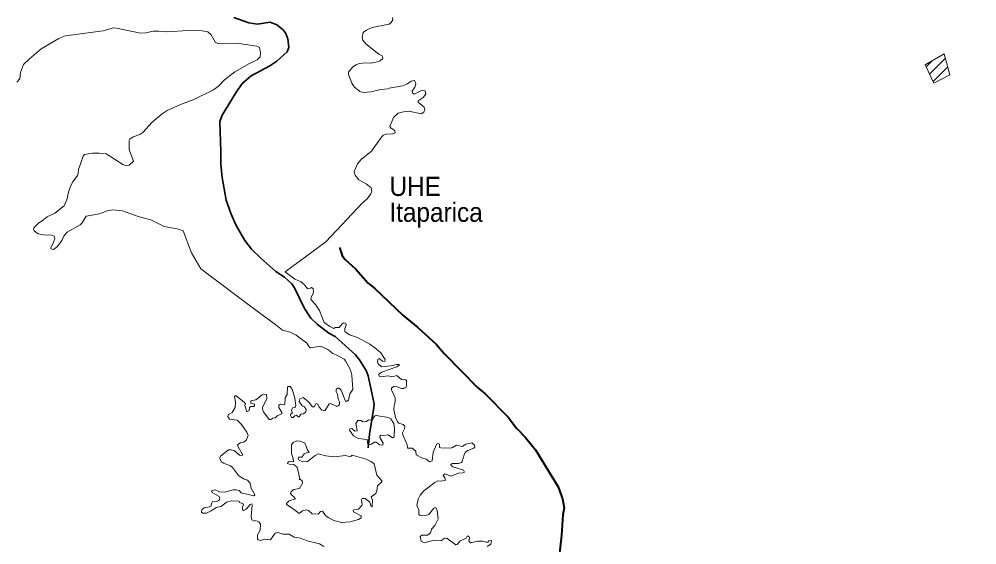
# Model space of a CAD drawing. Extents: x -1643653 to 4543381, y 1624270 to 13878484.
# Drawn here: x 577542 to 582541, y 8916252 to 8918997 of the extents above; entities that cross this region are included whole.
import ezdxf
from ezdxf.enums import TextEntityAlignment as Align

# ---------------------------------------------------------------- set-up
doc = ezdxf.new("R2010")
doc.units = 0
doc.header["$LTSCALE"] = 200
doc.linetypes.add('LONG_DASH_SHORT_DASH', pattern=[9.9, 6, -1.2, 1.5, -1.2])
doc.layers.add('6', color=7, linetype='Continuous', lineweight=13)
doc.layers.add('60', color=7, linetype='Continuous', lineweight=13)

msp = doc.modelspace()

# ---------------------------------------------------------------- linework, layer by layer
at = {"layer": '6'}
for p, q in [((582276.5, 8918748), (582308.9, 8918780.4)), ((582294.7, 8918709.6), (582376.4, 8918791.3)), ((582312.9, 8918671.2), (582388.6, 8918746.9)), ((578490.1, 8917693.2), (578784.8, 8917471.3))]:
    msp.add_line(p, q, dxfattribs=at)
at = {"layer": '6', "linetype": 'LONG_DASH_SHORT_DASH', "lineweight": 35}
msp.add_lwpolyline([(578662.2, 8919005.9), (578740.7, 8918978.3), (578785.6, 8918971), (578853, 8918981.3), (578886.8, 8918967.1), (578920.4, 8918940.8), (578934.7, 8918922.2), (578944.3, 8918894), (578949.9, 8918849), (578940.4, 8918826.6), (578886.4, 8918777.3), (578850.5, 8918753.1), (578753.6, 8918701.1), (578706.1, 8918660.5), (578672.4, 8918612.1), (578601.1, 8918496.3), (578590.2, 8918462.5), (578595.4, 8918305.1), (578594.6, 8918237.6), (578601, 8918170.3), (578622.6, 8918051), (578647.7, 8917978.3), (578674.1, 8917918.6), (578719.9, 8917840.4), (578754.5, 8917795.8), (578802.9, 8917748.3), (578882.1, 8917679.1), (578927.3, 8917649), (578965.1, 8917614.7), (578979.8, 8917594.3), (579031.7, 8917485.4), (579064.8, 8917435.4), (579097.3, 8917404.1), (579157.9, 8917356.5), (579191.2, 8917339.2), (579297.6, 8917243.3), (579319.2, 8917218.6), (579353.8, 8917162), (579364.1, 8917134.3), (579394.4, 8916988.5), (579393.5, 8916968.2), (579370.6, 8916829.9), (579363.6, 8916758.3)], dxfattribs=at)
at = {"layer": '6'}
for points in [[(579295.8, 8918182.3), (579291.5, 8918200.6), (579307.5, 8918242), (579327.8, 8918264.5), (579381, 8918307.3), (579422.1, 8918366.6), (579442.8, 8918390.3), (579458.5, 8918396.8), (579492.9, 8918398.1), (579504.6, 8918403.3), (579502.1, 8918414), (579491.2, 8918423.6), (579484.3, 8918425.4), (579477, 8918437), (579495.2, 8918484.1), (579521.1, 8918506.1), (579547.4, 8918513.1), (579576, 8918516.1), (579639.6, 8918503.2), (579655.1, 8918511.3), (579659.8, 8918523.3), (579656.9, 8918537.9), (579624.6, 8918563), (579625.6, 8918570.8), (579651.2, 8918588.3), (579665, 8918605.2), (579661.2, 8918622.9), (579642.5, 8918623.8), (579604.2, 8918605.7), (579595.9, 8918611.7), (579593.3, 8918620.7), (579607.5, 8918642.4), (579612.3, 8918657.9), (579611.4, 8918665.7), (579604.8, 8918676.1), (579589, 8918673.1), (579568.6, 8918658.8), (579543.1, 8918648), (579472.5, 8918637.1), (579466.2, 8918633.7), (579429.9, 8918630.3), (579378.4, 8918616.5), (579337.7, 8918613.6), (579320.5, 8918618.6), (579290.7, 8918643.6), (579278.5, 8918662.3), (579260.9, 8918708.6), (579260.8, 8918720.6), (579283.7, 8918747.4), (579301.1, 8918759.1), (579316.6, 8918764.7), (579347.4, 8918769.1), (579377.5, 8918767.2), (579405.6, 8918771.7), (579426.4, 8918779), (579440.6, 8918790.7), (579436.8, 8918806.1), (579419.9, 8918814.4), (579352.2, 8918867.1), (579336.1, 8918887.9), (579332.2, 8918899.6), (579337.8, 8918926.9), (579354.2, 8918939.8), (579384.9, 8918954.1), (579473.2, 8918970.6), (579483.9, 8918978.8), (579491.7, 8918993.8), (579490.8, 8919005.1)], [(577530.1, 8918668.4), (577544.6, 8918685.7), (577549.6, 8918717.7), (577565.3, 8918759.2), (577595.3, 8918789.2), (577657.2, 8918841.2), (577748.5, 8918896.2), (577783.4, 8918909.1), (577980.6, 8918936.4), (578032.5, 8918951.5), (578049.8, 8918950.2), (578175.2, 8918923), (578202.8, 8918925.1), (578240.9, 8918933.3), (578269.5, 8918934.2), (578316.9, 8918929.9), (578421.6, 8918937.2), (578497.7, 8918935.9), (578526.2, 8918930.3), (578544.1, 8918914.6), (578567.3, 8918875.5), (578580.7, 8918869.8), (578675.8, 8918871.9), (578783.4, 8918855.9), (578796.5, 8918849), (578802.1, 8918820.4), (578799.9, 8918799.8), (578784.2, 8918783.7), (578745, 8918765.1), (578668.1, 8918721.9), (578614, 8918680.4), (578582.9, 8918647.6)], [(578582.9, 8918647.6), (578556.1, 8918628.1), (578453.6, 8918577.1), (578384.4, 8918551.1), (578314.9, 8918519.8), (578289.2, 8918503.1), (578236.6, 8918459.1), (578187.2, 8918404.5), (578171.7, 8918394.2), (578137.1, 8918382.5), (578119.8, 8918370), (578116.4, 8918363.4), (578116.4, 8918315.5), (578139.3, 8918256.1), (578115.6, 8918233.9), (578097.5, 8918232.5), (578083.5, 8918238.1), (577996.1, 8918294.3), (577959.8, 8918297.8), (577925.3, 8918296.9), (577883.7, 8918289.5), (577875.1, 8918280.9), (577851.8, 8918211.1), (577850.5, 8918190.1), (577850.5, 8918190.1), (577846.6, 8918179.8), (577822.4, 8918148.2), (577810.3, 8918125.3), (577799.4, 8918094.1), (577789.9, 8918052.6), (577776.1, 8918021.5), (577728.5, 8917983.9), (577687.5, 8917964.5), (577662, 8917943.3), (577644.1, 8917933.6), (577618.3, 8917907.7), (577616.6, 8917899.6), (577620.9, 8917891.4), (577640.8, 8917876.2), (577678.8, 8917868.5), (577706.5, 8917869.8), (577723.8, 8917863.2), (577727.2, 8917851.6), (577719.5, 8917826.9), (577707.3, 8917804.8), (577707.5, 8917796.7), (577721.8, 8917793.9), (577742.6, 8917808.8), (577764.9, 8917840.7), (577774.6, 8917863.4), (577791.6, 8917884.4), (577859.9, 8917922), (577870.4, 8917933.4), (577892, 8917968.3), (577961.5, 8917980), (578000.5, 8917995.1), (578031.6, 8918000.3), (578081.7, 8917995.2), (578168.4, 8917964), (578228.8, 8917948.4), (578298, 8917913.9), (578366.3, 8917902.2), (578397.3, 8917891.4), (578441.2, 8917776.7), (578490.1, 8917693.2)], [(578930.2, 8917676.9), (579142.2, 8917833.7), (579335.3, 8918038.9), (579357.7, 8918059.2), (579378.4, 8918084.7), (579383.1, 8918098.5), (579378.9, 8918116.6), (579352.9, 8918137.4), (579315, 8918157.6), (579295.8, 8918182.3), (579295.8, 8918182.3)], [(579525.2, 8917189.8), (579524.8, 8917193.3), (579511.2, 8917193.8), (579483.6, 8917186.5), (579433, 8917181.8), (579416.5, 8917197.1), (579413.1, 8917206.5), (579414.3, 8917221.7), (579420.8, 8917225.1), (579438.1, 8917211.1), (579449.9, 8917208.6), (579451.7, 8917220), (579429.6, 8917254), (579405.4, 8917276.1), (579372.3, 8917299.4), (579307.2, 8917334.8), (579266.1, 8917349.2), (579241.9, 8917365.8), (579241.4, 8917382.3), (579249.1, 8917398.6), (579247.4, 8917406.9), (579236.3, 8917410.3), (579228.6, 8917406.1), (579211.6, 8917386.2), (579192.2, 8917386.1), (579184.8, 8917381.9), (579163.3, 8917391.7), (579134.8, 8917412.9), (579109.7, 8917475.8), (579088.5, 8917506.3), (579064.7, 8917532.7), (579065.9, 8917544.1), (579078.3, 8917570.1), (579077, 8917590.1), (579067.2, 8917595.1), (579063.4, 8917591.8), (579047.7, 8917589.2), (579032.8, 8917608.4), (579014.6, 8917624.9), (578981, 8917639.3), (578930.2, 8917676.9)], [(578784.8, 8917471.3), (578882.4, 8917401), (578916, 8917372.9), (578955.9, 8917361.9), (578987.8, 8917346.2), (579044.3, 8917305.4), (579055.8, 8917285.8), (579063, 8917280.4), (579114.1, 8917288.8), (579152.6, 8917271.4), (579179.4, 8917250.6), (579196.4, 8917244.7), (579238.8, 8917221.3), (579246.1, 8917213.2)], [(579246.1, 8917213.2), (579272, 8917166.4), (579278.8, 8917138.4), (579283, 8917063.6), (579268.4, 8917041), (579260.5, 8917007.6), (579254.2, 8917001.7), (579246.1, 8917002.5), (579223.2, 8917060.3), (579211.7, 8917070.4), (579204, 8917070.4), (579196, 8917062.4), (579196.4, 8917050.1), (579203.6, 8917036.1), (579206.6, 8917012.7), (579214.2, 8916998.7), (579214.2, 8916983.4), (579204, 8916976.3), (579197.2, 8916976.2), (579166.3, 8916989.7), (579160.8, 8916988.5), (579136.9, 8916951.5), (579120, 8916957.1), (579108.5, 8916971.1), (579101.6, 8916985.6), (579094.5, 8916990.2), (579089.8, 8916988), (579081.2, 8916971.9), (579072.7, 8916971.9), (579051.9, 8916999.1), (579024, 8917020.7), (579007.3, 8917014.4), (579003.5, 8917000.4), (579019, 8916977.3), (579019, 8916977.3), (579030.7, 8916971.9), (579040.8, 8916958.5), (579038.9, 8916945.5), (579025.6, 8916936.7), (579012, 8916934.1), (579004.3, 8916920.9), (578998.8, 8916921), (578989.1, 8916928.1), (578980.6, 8916924.7), (578972.7, 8916916.7), (578963.1, 8916917.2), (578957.6, 8916929.5), (578958.5, 8916934.5), (578969.1, 8916941.3), (578963.6, 8916954), (578969.1, 8916966.4), (578983.1, 8916969.8), (578986, 8916980.2), (578981, 8917017.8), (578967.8, 8917064.5), (578956.4, 8917078.9), (578945.3, 8917078.1), (578942.8, 8917074.6), (578941.5, 8917037.3), (578930.4, 8917019.4), (578929.2, 8916985.1), (578923.6, 8916982.5), (578905.8, 8916987.2), (578896.9, 8916981.2), (578897.3, 8916969.3), (578913.4, 8916943.5), (578912.2, 8916936.2), (578889.4, 8916926.1), (578879, 8916915.4), (578866.7, 8916912.8), (578856.5, 8916906.5), (578847.2, 8916906.5), (578816.6, 8916946), (578811.5, 8916960), (578811.5, 8916969.4), (578834, 8917016.1), (578833.1, 8917036.5), (578819.2, 8917038.6), (578810.7, 8917035.7), (578777.5, 8917009.3), (578751.2, 8917003.3), (578751.6, 8916991.5), (578769.8, 8916985.5), (578770.7, 8916979.1), (578766.4, 8916974.9), (578752, 8916974), (578744.8, 8916969.8), (578741.8, 8916953.2), (578730, 8916945.6), (578720.6, 8916978.7), (578722.7, 8916988.1), (578716.3, 8916997.3), (578675.1, 8917029.7), (578669.6, 8917029.7), (578666.2, 8917024.5), (578671.7, 8916996.7), (578668.7, 8916968.5), (578654.6, 8916942.9), (578635.1, 8916932.4), (578630.7, 8916922.7), (578631.7, 8916921.2)], [(579552, 8917069.7), (579561.3, 8917075.6), (579564.7, 8917085), (579564.3, 8917109.5), (579559.6, 8917112.9), (579537.1, 8917115.1), (579515.7, 8917134.7), (579509.1, 8917135.9), (579494.6, 8917128.3), (579464.1, 8917135), (579433.4, 8917128.7), (579423.3, 8917131.2), (579417.3, 8917140.9), (579417.3, 8917140.9), (579433.5, 8917154.2), (579514.2, 8917181.8), (579525.2, 8917189.5), (579525.2, 8917189.8)], [(579917.7, 8916773.9), (579905.3, 8916783.7), (579873.7, 8916777.8), (579854.9, 8916765.9), (579824.3, 8916772.2), (579804, 8916759.5), (579793.8, 8916756.9), (579742.8, 8916758.2), (579736, 8916760.8), (579735.9, 8916777.3), (579728.7, 8916781.6), (579722.4, 8916779.5), (579702.8, 8916736.5), (579697.3, 8916690.3), (579683.4, 8916685.2), (579668, 8916698.3), (579647.1, 8916703.6), (579614.5, 8916722.5), (579612.3, 8916740.7), (579594.1, 8916756.1), (579569, 8916757.4), (579566.8, 8916774.8), (579544.4, 8916825.7), (579542.7, 8916835.9), (579552.8, 8916857.2), (579555, 8916872.1), (579547.3, 8916880.6), (579523.5, 8916886.6), (579516.3, 8916894.6), (579507, 8916917.5), (579497.6, 8916958.4), (579498.9, 8916978.7), (579504.8, 8916999.2), (579504.8, 8917019.4), (579485.3, 8917060.5), (579485.3, 8917070.5), (579497.2, 8917078.5), (579506.5, 8917079.8), (579537.1, 8917068.4), (579549.4, 8917068), (579552, 8917069.7)], [(578631.7, 8916921.2), (578640.3, 8916907.8), (578679.7, 8916902.2), (578702.3, 8916880.2), (578729.5, 8916840.6), (578737.5, 8916822.4), (578726.5, 8916796.5), (578712.9, 8916787.1), (578697.6, 8916783.7), (578683.2, 8916775.6), (578682.8, 8916767.8), (578707.8, 8916723.8), (578705.3, 8916715.8), (578692.9, 8916720.8), (578663.6, 8916743.8), (578648.3, 8916748.4), (578635.2, 8916748), (578592.7, 8916714.5), (578589.3, 8916708.7)], [(579864.7, 8916634.6), (579861.4, 8916642.2), (579805, 8916658.7), (579796.7, 8916665.6), (579795.9, 8916670.7), (579803.2, 8916676.2), (579835.4, 8916676.7), (579851.1, 8916681.8), (579855.3, 8916686.5), (579864.7, 8916722.1), (579870.6, 8916733.1), (579883.4, 8916745), (579914.8, 8916756.9), (579919.9, 8916762.5), (579919.4, 8916772.6), (579917.7, 8916773.9)], [(578589.3, 8916708.7), (578588.8, 8916707.7), (578589.3, 8916700.1), (578598.2, 8916685.6), (578609.3, 8916678.3), (578645.4, 8916665.1), (578655.6, 8916655.8), (578686.2, 8916614.6), (578713.8, 8916596.8), (578734.5, 8916590), (578747.8, 8916573.3), (578753.7, 8916545.4), (578761.3, 8916530.1), (578765.6, 8916528.3), (578771.5, 8916511.8), (578766.4, 8916508.4), (578700.2, 8916523.2), (578689.5, 8916535.2), (578675.5, 8916539), (578675.5, 8916539), (578658.5, 8916539), (578615.9, 8916527.1), (578588, 8916528.8), (578564.2, 8916539), (578546, 8916533.9), (578550.2, 8916525.4), (578586.3, 8916505), (578590.1, 8916497.7), (578586.8, 8916486.4), (578577, 8916480.4), (578551.1, 8916476.1), (578544.7, 8916463.9), (578543.9, 8916454.1), (578536.1, 8916449.8), (578507.3, 8916444.7), (578497.4, 8916436.8)], [(580007.4, 8916273.3), (580005, 8916275.8), (579993.4, 8916271.9), (579988.7, 8916266.2), (579980.8, 8916265), (579958.6, 8916271.3), (579936.5, 8916271.3), (579898.3, 8916262), (579888.5, 8916271.8), (579893.2, 8916288), (579889.2, 8916296.8), (579880.4, 8916297.2), (579874.8, 8916287), (579841.8, 8916270.1), (579827.8, 8916253.1), (579822.2, 8916252.2), (579776.1, 8916284.1), (579776.1, 8916284.1), (579761.9, 8916285.8), (579744.5, 8916273.1), (579700.5, 8916273.9), (579656.1, 8916262.4), (579640, 8916271.3), (579634.5, 8916294.7), (579643.7, 8916301.5), (579673.1, 8916301.5), (579688.3, 8916313.8), (579694.3, 8916332.9), (579711.3, 8916352.4), (579729.1, 8916387.4), (579724.1, 8916431.5), (579716.4, 8916446.8), (579706.2, 8916443), (579680.1, 8916410.7), (579669.6, 8916406.4), (579636.5, 8916405.2), (579628.5, 8916410.7), (579627.6, 8916434), (579617.4, 8916457.2), (579624.2, 8916490.1), (579634.7, 8916512), (579654.4, 8916533.9), (579711.3, 8916577.2), (579727.5, 8916585.3), (579746.2, 8916584), (579767.8, 8916589.2), (579764.8, 8916601.4), (579755.1, 8916613.3), (579762.7, 8916622.2), (579796.7, 8916609.9), (579834.5, 8916626.9), (579859, 8916627.8), (579866.2, 8916631.2), (579864.7, 8916634.6)], [(578497.4, 8916436.8), (578495.8, 8916435.5), (578492.9, 8916423), (578500.7, 8916416.6), (578520.1, 8916417.9), (578544.7, 8916429), (578570.2, 8916446.4), (578597, 8916452.3), (578624.6, 8916474.4), (578650.8, 8916481.6), (578690.3, 8916479.5), (578692.6, 8916473.2), (578709.5, 8916467.6), (578713.8, 8916458.7), (578706.1, 8916446.7), (578707.4, 8916437), (578712.1, 8916431.9), (578727.3, 8916437.9), (578746.9, 8916462.5), (578756.1, 8916465.1), (578758.8, 8916459.5), (578752.4, 8916399.3), (578756.2, 8916382.7), (578768, 8916375.9), (578776.2, 8916379.7), (578793.6, 8916372), (578801.3, 8916359.2), (578800.4, 8916328.4), (578786.4, 8916304), (578785.6, 8916283.2), (578789, 8916277.3), (578801.2, 8916274.7), (578822.6, 8916281.5), (578853.9, 8916277.3), (578878.1, 8916312.9), (578892.2, 8916315.5), (578917.7, 8916308.3), (578951.5, 8916307), (578977.3, 8916292.1), (579011.2, 8916286.2), (579045.2, 8916273.5), (579108.9, 8916257.3), (579132.3, 8916243.2)], [(579985, 8916242.9), (580004.9, 8916254.8), (580007.4, 8916273.3)]]:
    msp.add_lwpolyline(points, dxfattribs=at)
for points in [[(582271.3, 8918759), (582316.7, 8918663.1), (582399.6, 8918706.8), (582369.9, 8918815)], [(579311.9, 8916806.7), (579287.8, 8916820.7), (579266.5, 8916850.4), (579268.6, 8916857.6), (579277.9, 8916858.5), (579293.7, 8916844.9), (579306, 8916847.8), (579300.1, 8916885.6), (579310.3, 8916901.8), (579327.1, 8916900.6), (579336.2, 8916894.2), (579354.4, 8916895.9), (579364.9, 8916904.3), (579383.7, 8916903.1), (579397.7, 8916925.9), (579404.7, 8916927.3), (579470, 8916917.5), (579481.4, 8916909), (579497.2, 8916885.2), (579501.4, 8916859.7), (579500.2, 8916815.2), (579490.3, 8916810.1), (579468.2, 8916825.8), (579442.7, 8916822.4), (579430.5, 8916824.9), (579426.2, 8916821), (579424.1, 8916811.8), (579441.9, 8916782), (579440.2, 8916771.4), (579422.4, 8916773.5), (579405, 8916787.9), (579396.9, 8916787.1), (579379.8, 8916776.9), (579361.3, 8916776.1), (579358.7, 8916801.1)], [(579270.4, 8916371.2), (579225.3, 8916369), (579184.5, 8916379.2), (579154.3, 8916394.1), (579141.6, 8916404.3), (579125.9, 8916427.7), (579115.6, 8916426.3), (579102.9, 8916411.1), (579071.1, 8916414.5), (579051.9, 8916431.1), (579041.7, 8916435.3), (579021.4, 8916429.8), (579003.5, 8916415.4), (578973, 8916439.5), (578937.7, 8916461.6), (578938.1, 8916466.8), (578951.7, 8916482), (578984.3, 8916491.4), (578976.3, 8916502.9), (578962.7, 8916513.5), (578958.9, 8916520.8), (578961, 8916530.5), (578976.2, 8916540.7), (579005.2, 8916546.7), (579020.1, 8916573.4), (579018.8, 8916585.7), (579011.2, 8916592.9), (579004, 8916593.8), (579006.5, 8916595.6), (578993.7, 8916657.9), (578975.1, 8916671.1), (578951.3, 8916672.4), (578942.6, 8916676.3), (578943.6, 8916681.1), (578950.8, 8916686.4), (578973.4, 8916685.7), (578972.5, 8916704.2), (578962.8, 8916726.2), (578963.2, 8916774.3), (578972.1, 8916786.7), (578991.6, 8916794.3), (579007.7, 8916792.6), (579030.7, 8916784.1), (579039.2, 8916773.1), (579045.2, 8916751.4), (579055.3, 8916734.4), (579050.6, 8916735.7), (579029.9, 8916727.6), (579017.1, 8916709.4), (579000.2, 8916708.9), (578998, 8916703.4), (579000.5, 8916695.4), (579023, 8916685.6), (579046.8, 8916686.4), (579087.6, 8916719.1), (579102.4, 8916727.1), (579142.9, 8916717), (579187, 8916711.9), (579231.2, 8916715.7), (579238.2, 8916719.5), (579264.4, 8916713.6), (579275.4, 8916715.3), (579279.7, 8916720.4), (579353.2, 8916698.9), (579378.2, 8916687.2), (579394.4, 8916674.1), (579408.8, 8916615.9), (579436, 8916584.4), (579433.8, 8916578.5), (579411.8, 8916560.2), (579409.7, 8916534.3), (579404.1, 8916520.7), (579378.7, 8916502.1), (579386.3, 8916485.9), (579384.2, 8916449.8), (579378.8, 8916451.2), (579372.7, 8916475.2), (579348.1, 8916493.1), (579332, 8916494.3), (579329.4, 8916487.3), (579333.2, 8916463.1), (579331.5, 8916456.5), (579312.8, 8916438.3), (579288.3, 8916435.3), (579285.6, 8916432.2), (579287, 8916424.2), (579328, 8916404), (579327.7, 8916393.3), (579312.8, 8916384.3)]]:
    msp.add_lwpolyline(points, close=True, dxfattribs=at)
at = {"layer": '6', "lineweight": 40}
msp.add_lwpolyline([(579213.9, 8917803.6), (579228.4, 8917763.4), (579242.2, 8917742.7), (579298.8, 8917690.5), (579364.6, 8917617.7), (579396.1, 8917591.3), (579545.7, 8917448.6), (579623.5, 8917387.3), (579718.5, 8917299.9), (579761.2, 8917250.1), (579934.8, 8917073.4), (579974.1, 8917041), (580094.4, 8916919), (580138.8, 8916860.8), (580185.2, 8916812.2), (580237.9, 8916747.8), (580356.4, 8916554.1), (580378.4, 8916492), (580386.2, 8916445.1), (580380.2, 8916408), (580372.4, 8916302.5), (580354.2, 8916132.1), (580354.2, 8916028.7)], dxfattribs=at)
at = {"layer": '60', "lineweight": 25}
msp.add_spline([(814781, 9009175.5), (814787.2, 9009173.4), (814796.9, 9009173.4), (814799.4, 9009172.4), (814805.1, 9009174.5), (814805.6, 9009176.5), (814811.7, 9009179.5), (814811.7, 9009179.5), (814801.5, 9009181), (814790.7, 9009181.5), (814784.1, 9009183.1), (814777.4, 9009185.1), (814778.4, 9009175.5)], degree=3, dxfattribs=at)

# ---------------------------------------------------------------- texts
at = {"layer": '6', "width": 0.95}
for s, p in [('UHE', (579609.2, 8918073.7)), ('Itaparica', (579718.2, 8917938.5))]:
    msp.add_text(s, height=100, dxfattribs=at).set_placement(p, align=Align.CENTER)

doc.saveas('drawing.dxf')
